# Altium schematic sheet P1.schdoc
size 594 x 419 mm; Symbol: Drawing-Symbol_A4; Company: 嘉立创EDA; Version: V1.0; Page Size: A4; @Project Name: BCIProject; @Update Date: 2026-07-25; @Create Date: 2026-07-25; Device: Drawing-Symbol_A4; @Board Name: Board1; @Page Name: P1; @Create Time: 19:43:27; @Page Count: 1; @Page No: 1; @Schematic Name: Schematic1; @Update Time: 19:43:27; @Assembly Variant: Basic; Border: 1; Title Block Position: 3; Size: A4; Width: 2338; Height: 1652; Region Start: 1; X Region Count: 6; Y Region Count: 4; Blade Width: 10
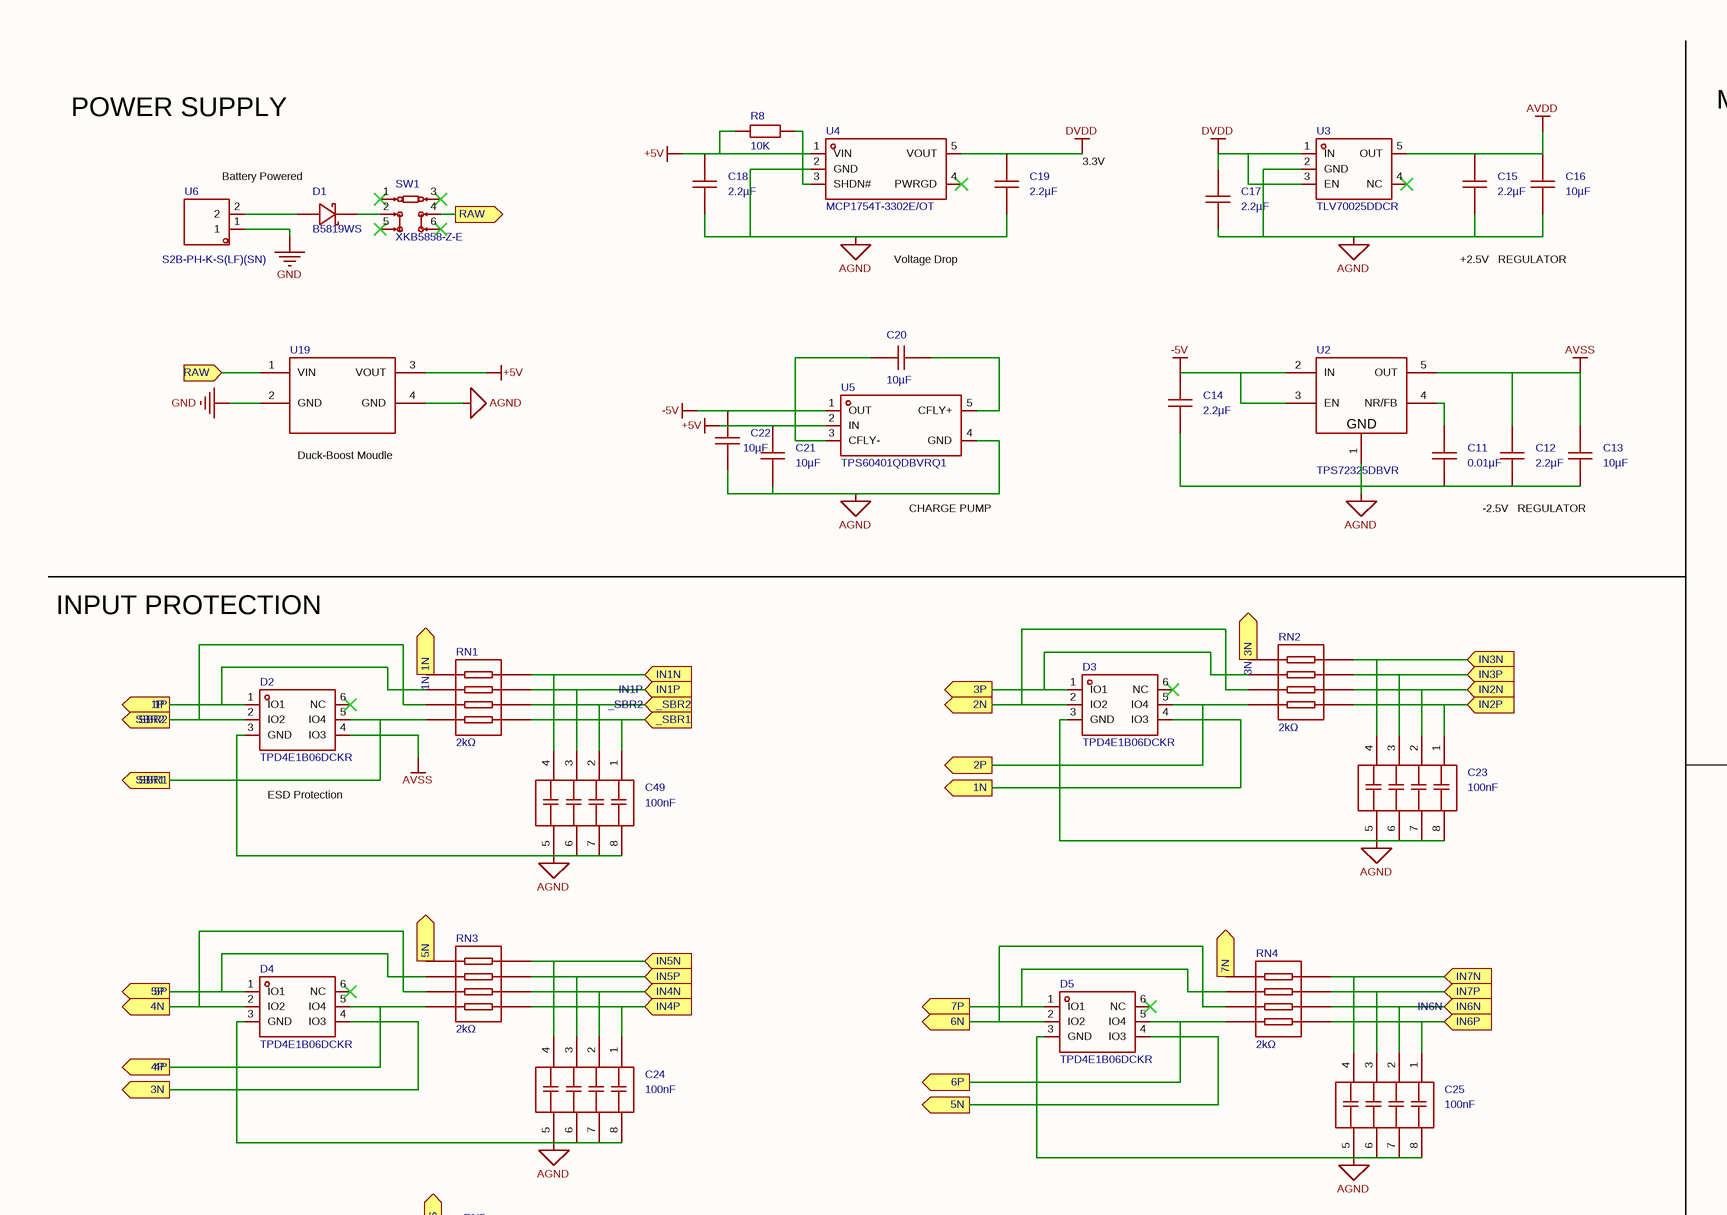
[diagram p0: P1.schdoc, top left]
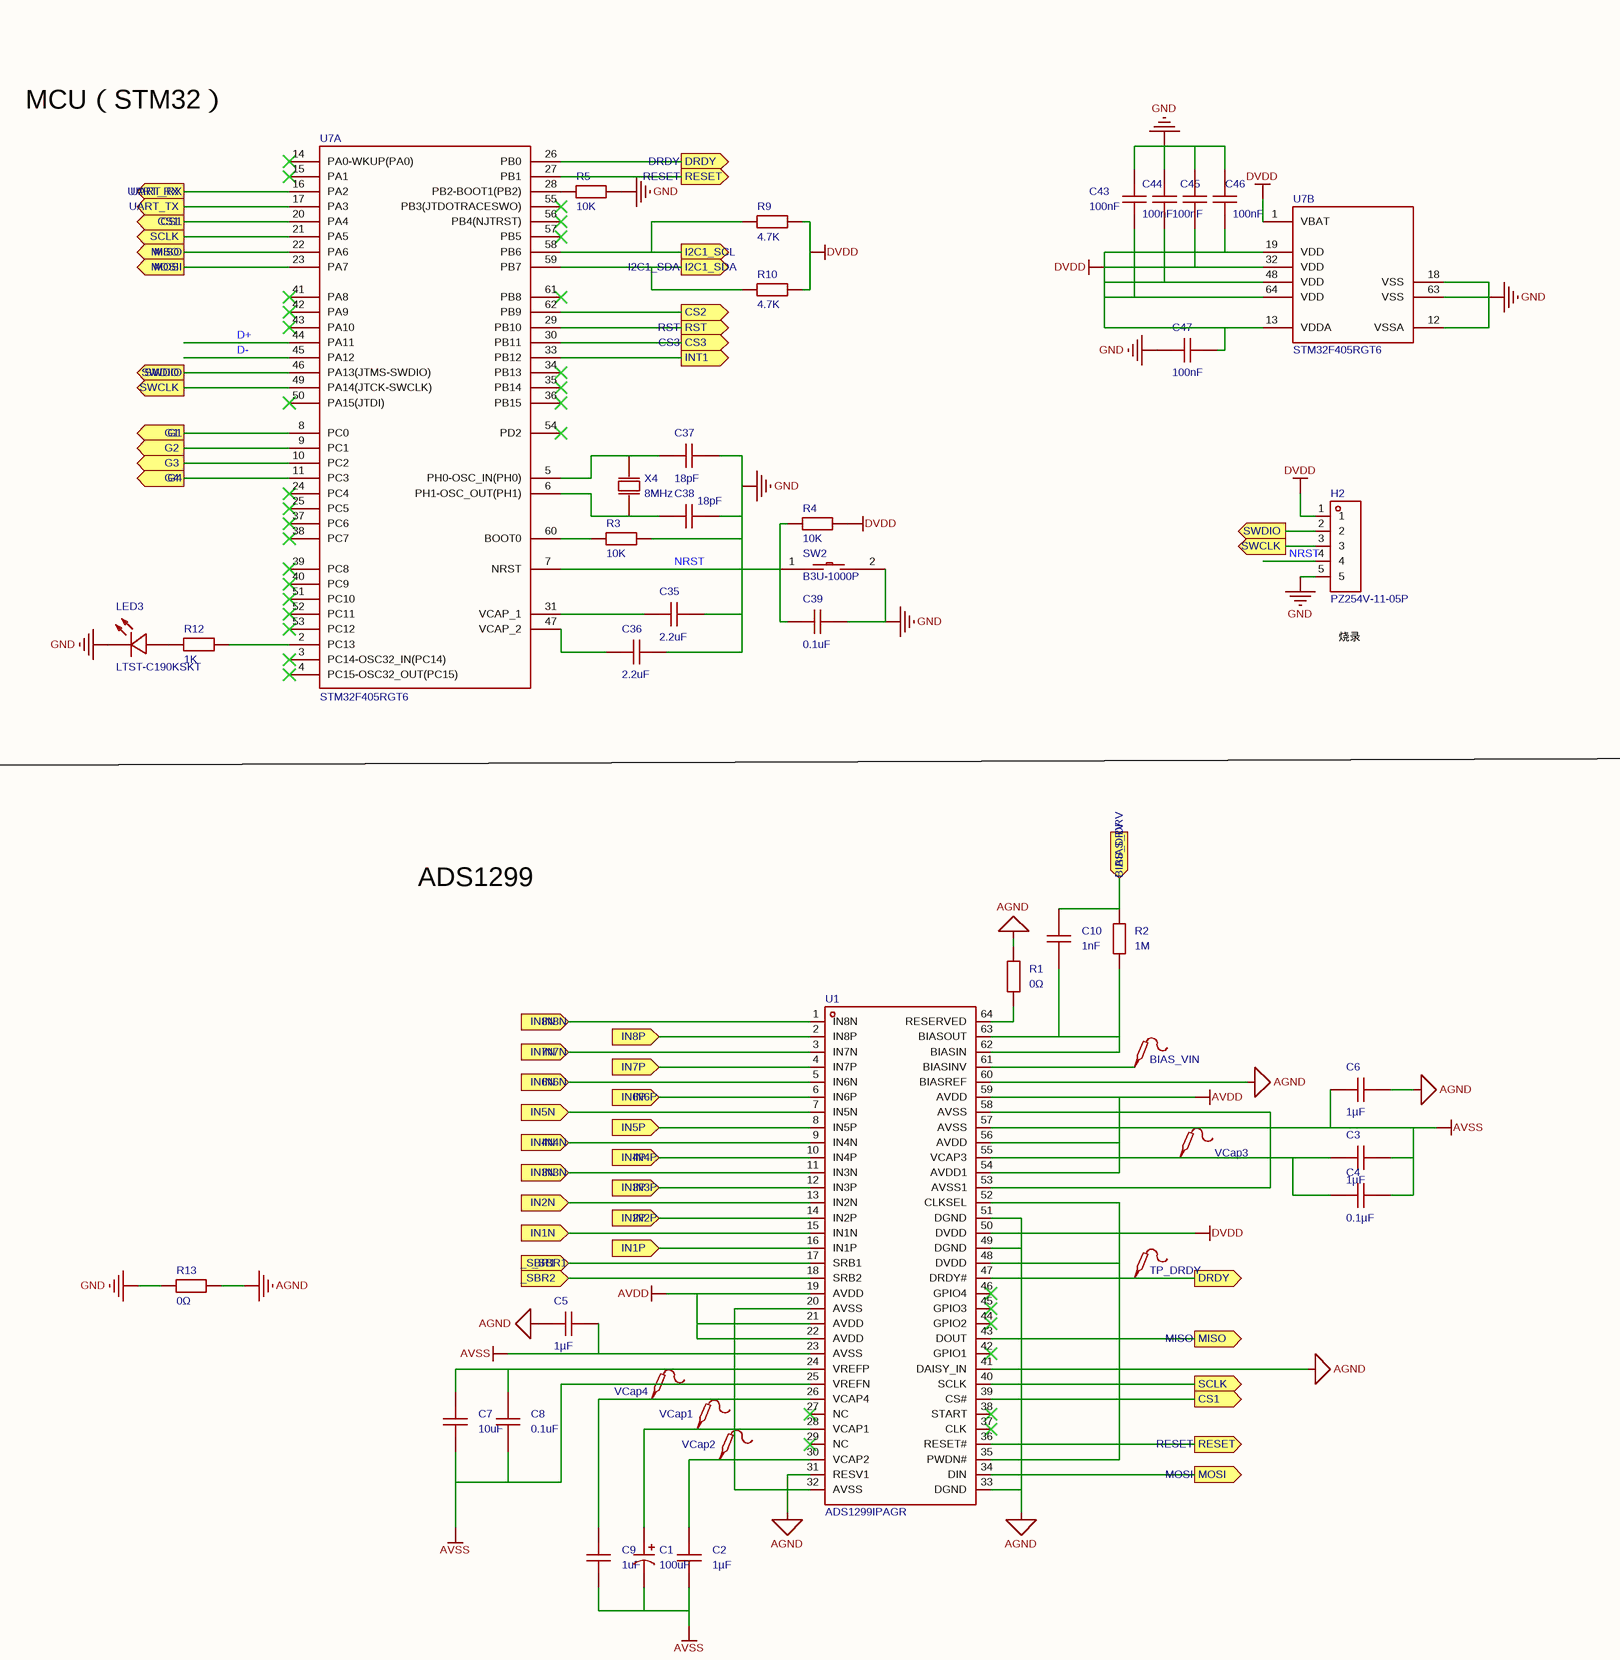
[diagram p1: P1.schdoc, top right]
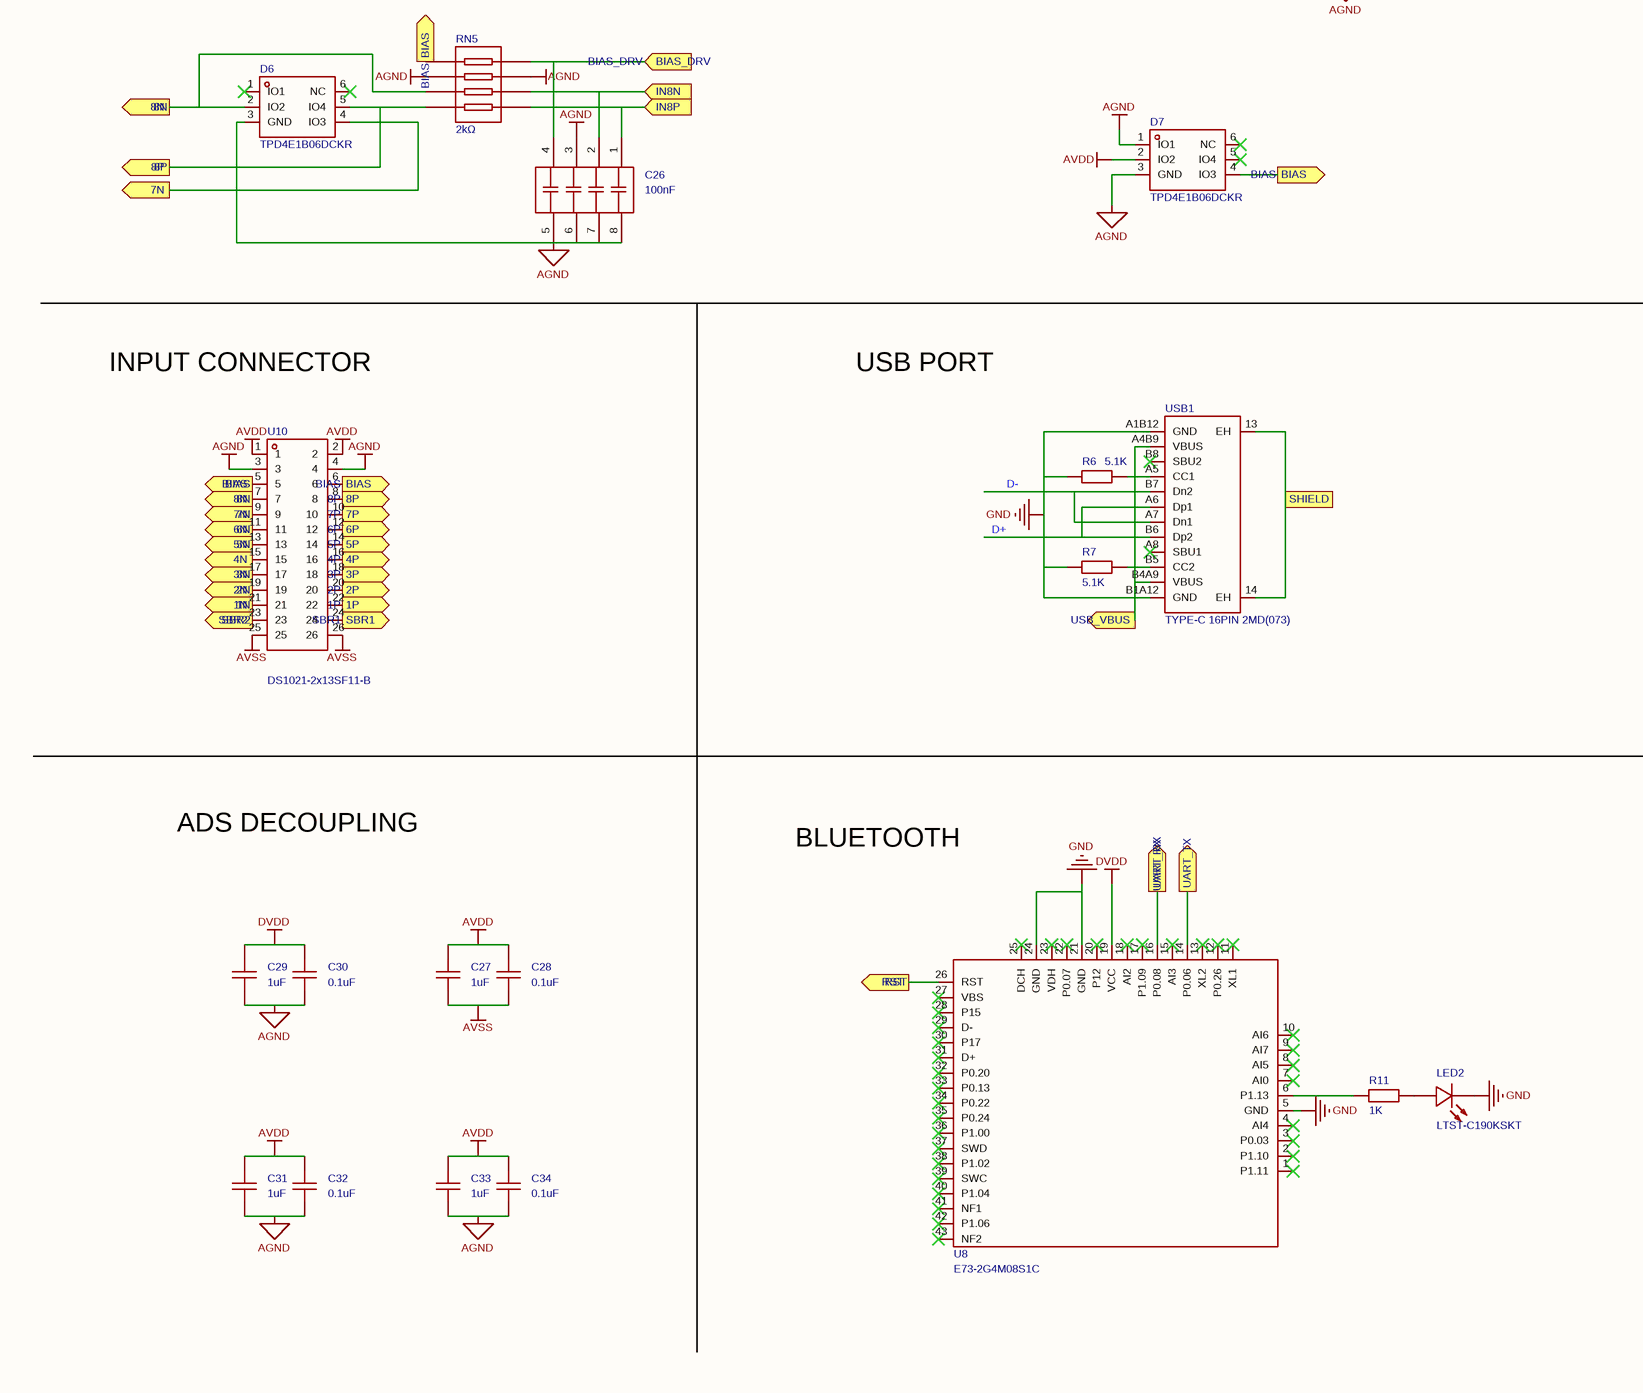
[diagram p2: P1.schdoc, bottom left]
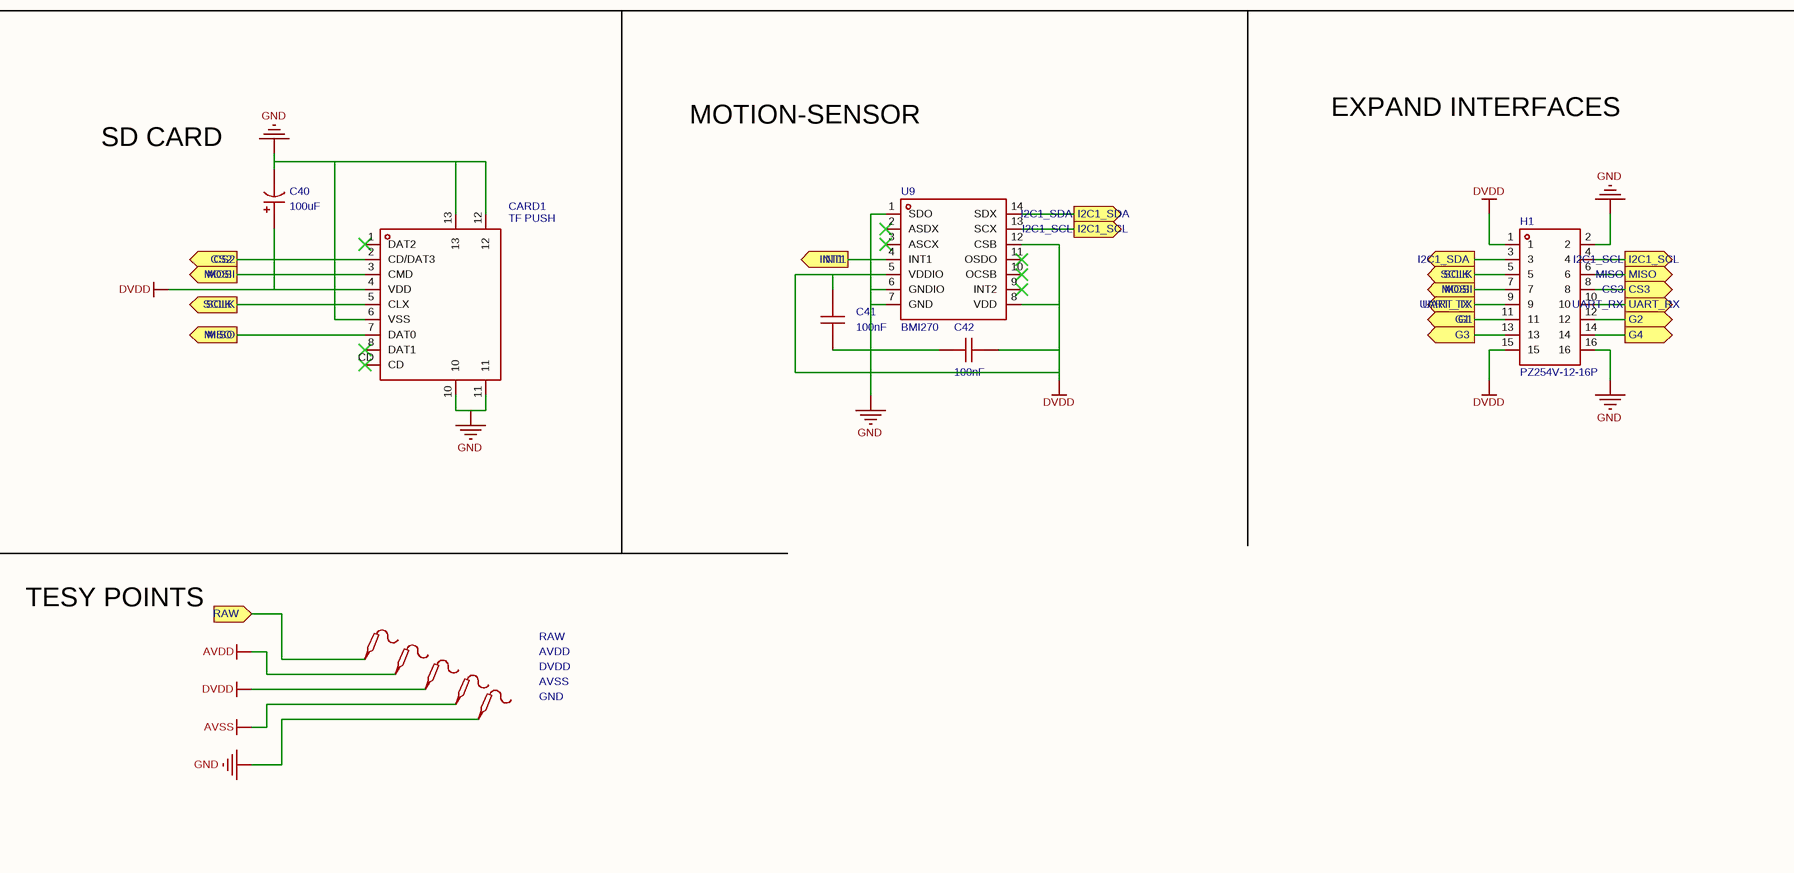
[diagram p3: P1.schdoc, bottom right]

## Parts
AVDD  (no value)  [Test-Point-0.5mm]
AVSS  (no value)  [Test-Point-0.5mm]
BIAS_VIN  (no value)  [Test-Point-0.5mm]
C1  100uF  [CAP-SMD_L7.3-W4.3-RD_177EC0013]
C2  1µF  [C0603]
C3  1µF  [C0603]
C4  0.1µF  [C0603]
C5  1µF  [C0603]
C6  1µF  [C0603]
C7  10uF  [C0603]
C8  0.1uF  [C0603]
C9  1uF  [C0603]
C10  1nF  [C0603]
C11  0.01µF  [C0603]
C12  2.2µF  [C0603]
C13  10µF  [C0603]
C14  2.2µF  [C0603]
C15  2.2µF  [C0603]
C16  10µF  [C0603]
C17  2.2µF  [C0603]
C18  2.2µF  [C0603]
C19  2.2µF  [C0603]
C20  10µF  [C0603]
C21  10µF  [C0603]
C22  10µF  [C0603]
C23  100nF  [CAP-ARRAY-SMD_6124-8P-L1.6-W3.2-BL]
C24  100nF  [CAP-ARRAY-SMD_6124-8P-L1.6-W3.2-BL]
C25  100nF  [CAP-ARRAY-SMD_6124-8P-L1.6-W3.2-BL]
C26  100nF  [CAP-ARRAY-SMD_6124-8P-L1.6-W3.2-BL]
C27  1uF  [C0603]
C28  0.1uF  [C0603]
C29  1uF  [C0603]
C30  0.1uF  [C0603]
C31  1uF  [C0603]
C32  0.1uF  [C0603]
C33  1uF  [C0603]
C34  0.1uF  [C0603]
C35  2.2uF  [C0603]
C36  2.2uF  [C0603]
C37  18pF  [C0603]
C38  18pF  [C0603]
C39  0.1uF  [C0603]
C40  100uF  [CAP-SMD_L7.3-W4.3-RD_177EC0013]
C41  100nF  [C0603]
C42  100nF  [C0603]
C43  100nF  [C0603]
C44  100nF  [C0603]
C45  100nF  [C0603]
C46  100nF  [C0603]
C47  100nF  [C0603]
C49  100nF  [CAP-ARRAY-SMD_6124-8P-L1.6-W3.2-BL]
CARD1  TF PUSH  [TF-SMD_TF-PUSH]
D1  B5819WS  [SOD-323_L1.7-W1.3-LS2.5-FD]
D2  TPD4E1B06DCKR  [SC-70-6_L2.2-W1.3-P0.65-LS2.1-BL]
D3  TPD4E1B06DCKR  [SC-70-6_L2.2-W1.3-P0.65-LS2.1-BL]
D4  TPD4E1B06DCKR  [SC-70-6_L2.2-W1.3-P0.65-LS2.1-BL]
D5  TPD4E1B06DCKR  [SC-70-6_L2.2-W1.3-P0.65-LS2.1-BL]
D6  TPD4E1B06DCKR  [SC-70-6_L2.2-W1.3-P0.65-LS2.1-BL]
D7  TPD4E1B06DCKR  [SC-70-6_L2.2-W1.3-P0.65-LS2.1-BL]
DVDD  (no value)  [Test-Point-0.5mm]
GND  (no value)  [Test-Point-0.5mm]
H1  PZ254V-12-16P  [HDR-TH_16P-P2.54-V-M-R2-C8-S2.54]
H2  PZ254V-11-05P  [HDR-TH_5P-P2.54-V-M]
LED2  LTST-C190KSKT  [LED0603-RD]
LED3  LTST-C190KSKT  [LED0603-RD]
R1  0Ω  [R0603]
R2  1M  [R0603]
R3  10K  [R0603]
R4  10K  [R0603]
R5  10K  [R0603]
R6  5.1K  [R0603]
R7  5.1K  [R0603]
R8  10K  [R0603]
R9  4.7K  [R0603]
R10  4.7K  [R0603]
R11  1K  [R0603]
R12  1K  [R0603]
R13  0Ω  [R0402]
RAW  (no value)  [Test-Point-0.5mm]
RN1  2kΩ  [RES-ARRAY-SMD_0603-8P-L3.2-W1.6-BL]
RN2  2kΩ  [RES-ARRAY-SMD_0603-8P-L3.2-W1.6-BL]
RN3  2kΩ  [RES-ARRAY-SMD_0603-8P-L3.2-W1.6-BL]
RN4  2kΩ  [RES-ARRAY-SMD_0603-8P-L3.2-W1.6-BL]
RN5  2kΩ  [RES-ARRAY-SMD_0603-8P-L3.2-W1.6-BL]
SW1  XKB5858-Z-E  [SW-TH_XKB5858-Z-E]
SW2  B3U-1000P  [KEY-SMD_B3U-1000PM]
TP_DRDY  (no value)  [Test-Point-0.5mm]
U1  ADS1299IPAGR  [TQFP-64_L10.0-W10.0-P0.50-LS12.0-TL]
U2  TPS72325DBVR  [SOT-23-5_L3.0-W1.7-P0.95-LS2.8-BR]
U3  TLV70025DDCR  [SOT-23-5_L3.0-W1.7-P0.95-LS2.8-BR]
U4  MCP1754T-3302E/OT  [SOT-23-5_L2.9-W1.6-P0.95-LS2.9-BL]
U5  TPS60401QDBVRQ1  [SOT-23-5_L2.9-W1.6-P0.95-LS2.8-BR]
U6  S2B-PH-K-S(LF)(SN)  [CONN-TH_S2B-PH-K-S-LF-SN]
U7  STM32F405RGT6  [LQFP-64_L10.0-W10.0-P0.50-LS12.0-BL]  (parts A,B of 2)
U8  E73-2G4M08S1C  [WIRELM-SMD_E73-2G4M08S1C]
U9  BMI270  [LGA-14_L3.0-W2.5-P0.50-BR]
U10  DS1021-2x13SF11-B  [HDR-TH_26P-P2.54-V-M-R2-C13-S2.54]
U19  (no value)  [tps63070模块]
USB1  TYPE-C 16PIN 2MD(073)  [USB-C-SMD_TYPE-C-16PIN-2MD-073]
VCap1  (no value)  [Test-Point-0.5mm]
VCap2  (no value)  [Test-Point-0.5mm]
VCap3  (no value)  [Test-Point-0.5mm]
VCap4  (no value)  [Test-Point-0.5mm]
X4  8MHz  [CRYSTAL-SMD_L5.0-W3.2]

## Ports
1N (out), 1P (out), 2N (out), 2P (out), 3N (out), 3P (out), 4N (out), 4P (out), 5N (out), 5P (out), 6N (out), 6P (out), 7N (out), 7P (out), 8N (out), 8P (out), _SBR1 (in), _SBR2 (in), BIAS (out), BIAS_DRV (in), CS1 (out), CS2 (out), CS3 (out), DRDY (out), G1 (out), G2 (out), G3 (out), G4 (out), I2C1_SCL (out), I2C1_SDA (out), IN1N (in), IN1P (in), IN2N (in), IN2P (in), IN3N (in), IN3P (in), IN4N (in), IN4P (in), IN5N (in), IN5P (in), IN6N (in), IN6P (in), IN7N (in), IN7P (in), IN8N (in), IN8P (in), INT1 (out), MISO (out), MOSI (out), RAW (in), RAW (out), RESET (out), RST (out), SBR1 (out), SBR2 (out), SCLK (out), SHIELD (out), SWCLK (out), SWDIO (out), UART_RX (out), UART_TX (out), USB_VBUS (out)

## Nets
+5V: C18.2 C21.2 R8.1 U4.1(VIN) U5.2(IN) U19.3(VOUT)
-5V: C14.2 C22.2 U2.2(IN) U2.3(EN) U5.1(OUT)
AGND: C5.1 C6.2 C11.1 C12.1 C13.2 C14.1 C15.1 C16.1 C17.1 C18.1 C19.1 C21.1 C22.1 C23.5 C23.6 C23.7 C23.8 C24.5 C24.6 C24.7 C24.8 C25.5 C25.6 C25.7 C25.8 C26.3 C26.5 C26.6 C26.7 C26.8 C29.1 C30.1 C31.1 C32.1 C33.1 C34.1 C49.5 C49.6 C49.7 C49.8 D2.3(GND) D3.3(GND) D4.3(GND) D5.3(GND) D6.3(GND) D7.1(IO1) D7.3(GND) R1.2 R13.1 RN5.2 RN5.7 U1.31(RESV1) U1.33(DGND) U1.41(DAISY_IN) U1.49(DGND) U1.51(DGND) U1.60(BIASREF) U2.1(GND) U3.2(GND) U4.2(GND) U5.4(GND) U10.3 U10.4 U19.4(GND)
AVDD: AVDD.1 C15.2 C16.2 C27.2 C28.2 C31.2 C32.2 C33.2 C34.2 D7.2(IO2) U1.19(AVDD) U1.21(AVDD) U1.22(AVDD) U1.54(AVDD1) U1.56(AVDD) U1.59(AVDD) U3.5(OUT) U10.1 U10.2
AVSS: AVSS.1 C1.1 C2.1 C3.2 C4.2 C5.2 C6.1 C7.1 C8.1 C9.1 C12.2 C13.1 C27.1 C28.1 D2.4(IO3) U1.20(AVSS) U1.23(AVSS) U1.25(VREFN) U1.32(AVSS) U1.53(AVSS1) U1.57(AVSS) U1.58(AVSS) U2.5(OUT) U10.25 U10.26
DVDD: C17.2 C19.2 C29.2 C30.2 C40.2 C41.2 C42.2 C43.1 C44.1 C45.1 C46.1 C47.2 CARD1.4(VDD) DVDD.1 H1.1 H1.15 H2.1 R4.2 R9.2 R10.2 U1.35(PWDN#) U1.48(DVDD) U1.50(DVDD) U1.52(CLKSEL) U3.1(IN) U3.3(EN) U4.5(VOUT) U7.1(VBAT) U7.13(VDDA) U7.19(VDD) U7.32(VDD) U7.48(VDD) U7.64(VDD) U8.19(VCC) U9.5(VDDIO) U9.8(VDD) U9.12(CSB)
GND: C35.2 C36.2 C37.2 C38.2 C39.2 C40.1 C41.1 C42.1 C43.2 C44.2 C45.2 C46.2 C47.1 CARD1.6(VSS) CARD1.10 CARD1.11 CARD1.12 CARD1.13 GND.1 H1.2 H1.16 H2.5 LED2.1(-) LED3.1(-) R3.2 R5.2 R6.1 R7.1 R13.2 SW2.2 U6.1 U7.12(VSSA) U7.18(VSS) U7.63(VSS) U8.5(GND) U8.21(GND) U8.24(GND) U9.1(SDO) U9.6(GNDIO) U9.7(GND) U19.2(GND) USB1.A1B12(GND) USB1.B1A12(GND)
1N: D3.4(IO3) RN1.1 U10.21 ; port 1N
1P: D2.1(IO1) RN1.2 U10.22 ; port 1P
2N: D3.2(IO2) RN2.3 U10.19 ; port 2N
2P: D3.5(IO4) RN2.4 U10.20 ; port 2P
3N: D4.4(IO3) RN2.1 U10.17 ; port 3N
3P: D3.1(IO1) RN2.2 U10.18 ; port 3P
4N: D4.2(IO2) RN3.3 U10.15 ; port 4N
4P: D4.5(IO4) RN3.4 U10.16 ; port 4P
5N: D5.4(IO3) RN3.1 U10.13 ; port 5N
5P: D4.1(IO1) RN3.2 U10.14 ; port 5P
6N: D5.2(IO2) RN4.3 U10.11 ; port 6N
6P: D5.5(IO4) RN4.4 U10.12 ; port 6P
7N: D6.4(IO3) RN4.1 U10.9 ; port 7N
7P: D5.1(IO1) RN4.2 U10.10 ; port 7P
8N: D6.2(IO2) RN5.3 U10.7 ; port 8N
8P: D6.5(IO4) RN5.4 U10.8 ; port 8P
_SBR1: C49.1 RN1.5 U1.17(SRB1) ; port _SBR1
_SBR2: C49.2 RN1.6 U1.18(SRB2) ; port _SBR2
BIAS: D7.4(IO3) RN5.1 U10.5 U10.6 ; port BIAS
BIAS_DRV: C10.2 C26.4 R2.2 RN5.8 ; port BIAS_DRV
CS1: U1.39(CS#) U7.20(PA4) ; port CS1
CS2: CARD1.2(CD/DAT3) U7.62(PB9) ; port CS2
CS3: H1.8 U7.30(PB11) ; port CS3
D+: U7.44(PA11) USB1.A6(Dp1) USB1.B6(Dp2)
D-: U7.45(PA12) USB1.A7(Dn1) USB1.B7(Dn2)
DRDY: TP_DRDY.1 U1.47(DRDY#) U7.26(PB0) ; port DRDY
G1: H1.11 U7.8(PC0) ; port G1
G2: H1.12 U7.9(PC1) ; port G2
G3: H1.13 U7.10(PC2) ; port G3
G4: H1.14 U7.11(PC3) ; port G4
I2C1_SCL: H1.4 R9.1 U7.58(PB6) U9.13(SCX) ; port I2C1_SCL
I2C1_SDA: H1.3 R10.1 U7.59(PB7) U9.14(SDX) ; port I2C1_SDA
IN1N: C49.4 RN1.8 U1.15(IN1N) ; port IN1N
IN1P: C49.3 RN1.7 U1.16(IN1P) ; port IN1P
IN2N: C23.2 RN2.6 U1.13(IN2N) ; port IN2N
IN2P: C23.1 RN2.5 U1.14(IN2P) ; port IN2P
IN3N: C23.4 RN2.8 U1.11(IN3N) ; port IN3N
IN3P: C23.3 RN2.7 U1.12(IN3P) ; port IN3P
IN4N: C24.2 RN3.6 U1.9(IN4N) ; port IN4N
IN4P: C24.1 RN3.5 U1.10(IN4P) ; port IN4P
IN5N: C24.4 RN3.8 U1.7(IN5N) ; port IN5N
IN5P: C24.3 RN3.7 U1.8(IN5P) ; port IN5P
IN6N: C25.2 RN4.6 U1.5(IN6N) ; port IN6N
IN6P: C25.1 RN4.5 U1.6(IN6P) ; port IN6P
IN7N: C25.4 RN4.8 U1.3(IN7N) ; port IN7N
IN7P: C25.3 RN4.7 U1.4(IN7P) ; port IN7P
IN8N: C26.2 RN5.6 U1.1(IN8N) ; port IN8N
IN8P: C26.1 RN5.5 U1.2(IN8P) ; port IN8P
INT1: U7.33(PB12) U9.4(INT1) ; port INT1
MISO: CARD1.7(DAT0) H1.6 U1.43(DOUT) U7.22(PA6) ; port MISO
MOSI: CARD1.3(CMD) H1.7 U1.34(DIN) U7.23(PA7) ; port MOSI
NRST: C39.1 H2.4 R4.1 SW2.1 U7.7(NRST)
RAW: RAW.1 SW1.4 U19.1(VIN) ; port RAW
RESET: U1.36(RESET#) U7.27(PB1) ; port RESET
RST: U7.29(PB10) U8.26(RST) ; port RST
SBR1: D2.5(IO4) RN1.4 U10.24 ; port SBR1
SBR2: D2.2(IO2) RN1.3 U10.23 ; port SBR2
SCLK: CARD1.5(CLX) H1.5 U1.40(SCLK) U7.21(PA5) ; port SCLK
SHIELD: USB1.13(EH) USB1.14(EH) ; port SHIELD
SWCLK: H2.3 U7.49(PA14(JTCK-SWCLK)) ; port SWCLK
SWDIO: H2.2 U7.46(PA13(JTMS-SWDIO)) ; port SWDIO
UART_RX: H1.10 U7.16(PA2) U8.16(P0.08) ; port UART_RX
UART_TX: H1.9 U7.17(PA3) U8.14(P0.06) ; port UART_TX
USB_VBUS: USB1.A4B9(VBUS) USB1.B4A9(VBUS) ; port USB_VBUS
NetBIAS_VIN_1: BIAS_VIN.1 U1.61(BIASINV)
NetC1_2: C1.2 U1.28(VCAP1) VCap1.1
NetC2_2: C2.2 U1.30(VCAP2) VCap2.1
NetC3_1: C3.1 C4.1 U1.55(VCAP3) VCap3.1
NetC7_2: C7.2 C8.2 U1.24(VREFP)
NetC9_2: C9.2 U1.26(VCAP4) VCap4.1
NetC10_1: C10.1 R2.1 U1.62(BIASIN) U1.63(BIASOUT)
NetC11_2: C11.2 U2.4(NR/FB)
NetC20_1: C20.1 U5.3(CFLY-)
NetC20_2: C20.2 U5.5(CFLY+)
NetC35_1: C35.1 U7.31(VCAP_1)
NetC36_1: C36.1 U7.47(VCAP_2)
NetC37_1: C37.1 U7.5(PH0-OSC_IN(PH0)) X4.2(OSC2)
NetC38_1: C38.1 U7.6(PH1-OSC_OUT(PH1)) X4.1(OSC1)
NetD1_1: D1.1(A) U6.2
NetD1_2: D1.2(K) SW1.2
NetLED2_2: LED2.2(+) R11.2
NetLED3_2: LED3.2(+) R12.2
NetR1_1: R1.1 U1.64(RESERVED)
NetR3_1: R3.1 U7.60(BOOT0)
NetR5_1: R5.1 U7.28(PB2-BOOT1(PB2))
NetR6_2: R6.2 USB1.A5(CC1)
NetR7_2: R7.2 USB1.B5(CC2)
NetR8_2: R8.2 U4.3(SHDN#)
NetR11_1: R11.1 U8.6(P1.13)
NetR12_1: R12.1 U7.2(PC13)

Not connected (* = marked no-connect by the designer): CARD1 1(DAT2)* 8(DAT1)* CD*; D2 6(NC)*; D3 6(NC)*; D4 6(NC)*; D5 6(NC)*; D6 1(IO1)* 6(NC)*; D7 5(IO4)* 6(NC)*; SW1 1* 3* 5* 6*; U1 27(NC)* 29(NC)* 37(CLK)* 38(START)* 42(GPIO1)* 44(GPIO2)* 45(GPIO3)* 46(GPIO4)*; U3 4(NC)*; U4 4(PWRGD)*; U7 3(PC14-OSC32_IN(PC14))* 4(PC15-OSC32_OUT(PC15))* 14(PA0-WKUP(PA0))* 15(PA1)* 24(PC4)* 25(PC5)* 34(PB13)* 35(PB14)* 36(PB15)* 37(PC6)* 38(PC7)* 39(PC8)* 40(PC9)* 41(PA8)* 42(PA9)* 43(PA10)* 50(PA15(JTDI))* 51(PC10)* 52(PC11)* 53(PC12)* 54(PD2)* 55(PB3(JTDOTRACESWO))* 56(PB4(NJTRST))* 57(PB5)* 61(PB8)*; U8 1(P1.11)* 2(P1.10)* 3(P0.03)* 4(AI4)* 7(AI0)* 8(AI5)* 9(AI7)* 10(AI6)* 11(XL1)* 12(P0.26)* 13(XL2)* 15(AI3)* 17(P1.09)* 18(AI2)* 20(P12)* 22(P0.07)* 23(VDH)* 25(DCH)* 27(VBS)* 28(P15)* 29(D-)* 30(P17)* 31(D+)* 32(P0.20)* 33(P0.13)* 34(P0.22)* 35(P0.24)* 36(P1.00)* 37(SWD)* 38(P1.02)* 39(SWC)* 40(P1.04)* 41(NF1)* 42(P1.06)* 43(NF2)*; U9 2(ASDX)* 3(ASCX)* 9(INT2)* 10(OCSB)* 11(OSDO)*; USB1 A8(SBU1)* B8(SBU2)*

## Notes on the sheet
- POWER SUPPLY
- MCU（STM32）
- Battery Powered
- 3.3V
- Voltage Drop
- +2.5V   REGULATOR
- (near U19) Duck-Boost Moudle
- CHARGE PUMP
- -2.5V   REGULATOR
- INPUT PROTECTION
- (near H2) 烧录
- (near D2) ESD Protection
- ADS1299
- INPUT CONNECTOR
- USB PORT
- EXPAND INTERFACES
- SD CARD
- MOTION-SENSOR
- ADS DECOUPLING
- BLUETOOTH
- TESY POINTS

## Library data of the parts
AVDD AVSS BIAS_VIN DVDD GND RAW TP_DRDY VCap1-VCap4 = Test-Point: Test Point 测试点; AddInBom: yes
C1 C40 = TA10R0M100AR40: 容值:100uF;精度:±20%;额定电压:10V;等效串联电阻(ESR):40mΩ@100kHz;; Manufacturer: JIERR(捷而瑞); AddInBom: yes; ModelId: 57a4bba5c484496b9c973bf4fd310b240819f05c4eef4c71ace90d822a990e87; ModelTransform: 287.401,169.291,0,0,0,0,0,0,0; Tolerance: ±20%; Voltage Rating: 10V; Current - Leakage: 100uA@20℃,2min; Ripple Current: 3.2A@100kHz
C2-C22 C27-C39 C41-C47 = CAP_0603: Symbol: Capacitance; ConvertToPcb: yes; ModelId: ac125912035d415993ca9572d50418b10819f05c4eef4c71ace90d822a990e87; ModelName: C0603_L1.6-W0.8-H0.8; ModelTransform: 62.992,31.496,0,0,0,0,0,0,0
C23-C26 C49 = 6124B104K500NT: 容值:100nF;精度:±10%;额定电压:50V;温度系数:X7R;电路形式:独立;; Manufacturer: FH(风华); 3D Model: f2e49f0a400c466dbdd055404a35ee7a; 3D Model Transform: 125.984,63.7794,0,0,0,0,0,0,0; Tolerance: ±10%; Rated Voltage: 50V; Temperature Coefficient: X7R; Number of Capacitors: 4; Circuit Type: 独立; AddInBom: yes; ModelName: CAP-ARRAY-SMD_L1.6-W3.2-H0.9-P0.8
CARD1 = TF PUSH: 卡连接方式:自弹式;卡类型:MicroSD卡(TF卡);连接器类型:卡座;本体最大高度:2mm;工作温度:-25℃~+90℃;; Manufacturer: SHOU HAN(首韩); AddInBom: yes; ModelId: 2d6270e77c9a43c6bb0aca962ba811a20819f05c4eef4c71ace90d822a990e87; ModelTransform: 635.826,598.424,0,0,0,0,0.002,-82.441,-23.622; Card Connection Mode: 自弹式; Connector Type: 卡座; Additional Card Detection Pins: 无
D1 = B5819WS_C7420331: 二极管配置:独立式;正向压降(Vf):600mV@1.0A;直流反向耐压(Vr):40V;整流电流:1A;; Manufacturer: R+O(宏嘉诚); AddInBom: yes; ModelId: 0f2f330c645944df9245ac3c3fec34560819f05c4eef4c71ace90d822a990e87; ModelTransform: 98.425,49.2125,0,180,0,0,0,0,0; Diode Configuration: 独立式; Voltage - DC Reverse(Vr): 40V; Current - Rectified: 1A; Reverse Leakage Current (Ir): 1mA@40V; Operating Junction Temperature Range: -55℃~+150℃; Non-Repetitive Peak Forward Surge Current: 10A
D2-D7 = TPD4E1B06DCKR: TPD4E1B06 采用 SOT 和 SC70 封装且具有 0.5nA 最大泄漏电流的四路 0.7pF、±5.5V、±12kV ESD 保护二极管; Manufacturer: TI(德州仪器); AddInBom: yes; ModelId: 7779600a2eb94c6fae04993c10cd58cb0819f05c4eef4c71ace90d822a990e87; ModelName: SC-70-6_L2.0-W1.3-H1.0-P0.65; ModelTransform: 82.677,78.74,0,90,0,0,0,0.0005,0
H1 = PZ254V-12-16P: 插针结构:2x8P;间距:2.54mm;行距:2.54mm;圆针/方针:方针;安装方式:直插;排数:双排;总PIN位数:16P;额定电流:-;额定电压:-;配合针长度:6mm;塑高:2.5mm;端接针长度:3mm;触头材质:黄铜;触头镀层:-;工作温度:-40℃~+105℃;颜色:黑色;; Manufacturer: XFCN(兴飞); AddInBom: yes; ModelId: 4229ed04564d49dfa51d40f734d422b60819f05c4eef4c71ace90d822a990e87; ModelName: HDR2.54-M-LI-2X8P; ModelTransform: 799.99844,200,0,0,0,0,0,0,-118.11; Pin Structure: 2x8P; Pitch: 2.54mm; Circluar Pins/Square Pins: 方针
H2 = PZ254V-11-05P: 插针结构:1x5P;间距:2.54mm;行距:-;圆针/方针:方针;安装方式:直插;排数:单排;总PIN位数:5P;额定电流:3A;额定电压:250V;配合针长度:6mm;塑高:2.5mm;端接针长度:3mm;触头材质:黄铜;触头镀层:-;工作温度:-40℃~+105℃;颜色:黑色;; Manufacturer: XFCN(兴飞); AddInBom: yes; ModelId: 47d466e4a34f4fc5bc626cf773a24dd50819f05c4eef4c71ace90d822a990e87; ModelName: HDR-TH_5P-P2.54-M-LI-1X5P; ModelTransform: 499.999,100,0,0,0,0,0,0,-118.11; Pin Structure: 1x5P; Pitch: 2.54mm; Circluar Pins/Square Pins: 方针; Current Rating: 3A; Voltage Rating (Max): 250V
LED2 LED3 = LTST-C190KSKT: 灯头类型:-;发光颜色:黄色;正向压降(Vf):2.1V;功率:75mW;正向电流:20mA;波长:584.5nm~597nm;二极管配置:独立二极管;透镜颜色:无色透明透镜;色温:-;发光强度:104mcd;发光角度:130°;载带方式:-;工作温度:-30℃~+85℃;; Manufacturer: LITEON(光宝); AddInBom: yes; ModelId: 1f0d29a91be547639d425604e9b96ebb0819f05c4eef4c71ace90d822a990e87; ModelTransform: 63.7794,32.283,0,0,0,0,0,0,0; Illumination Color: 黄色; Voltage - Forward(Vf): 2.1V; Power(Watts): 75mW; Forward Current: 20mA; Peak Wavelength: 588nm; Diode Configuration: 独立二极管; Lens Color: 无色透明透镜; Luminous Intensity: 104mcd; Viewing Angle: 130°
R1-R12 = Res_0603: Symbol: 电阻; ConvertToPcb: yes; ModelId: fc143cca1e79419f9cd78b61e9279f080819f05c4eef4c71ace90d822a990e87; ModelTransform: 31.8897,63.7794,0,90,0,0,0,0,0
R13 = 0402WGF0000TCE: 电阻类型:厚膜电阻;阻值:0Ω;精度:±1%;功率:62.5mW;最大工作电压:50V;温度系数:±800ppm/℃;; Manufacturer: UNI-ROYAL(厚声); 3D Model: 671aefced39d4c318694bba8bd8efd39; 3D Model Transform: 39.37,19.685,0,0,0,0,0,0.0005,0; Tolerance: ±1%; Power(Watts): 62.5mW; Overload Voltage (Max): 50V; AddInBom: yes; ModelName: R0402_L1.0-W0.5-H0.5
RN1-RN5 = 4D03WGF2001T5E: 电阻器数:4;阻值:2kΩ;精度:±1%;单个元件功率:62.5mW;温度系数:±200ppm/℃;; Manufacturer: UNI-ROYAL(厚声); AddInBom: yes; ModelId: edf39f9a2dca4b9a94267f442dd4f95a0819f05c4eef4c71ace90d822a990e87; ModelName: R0603-8P_L3.2-W1.6-H0.6; ModelTransform: 125.984,62.992,0,0,0,0,0,0,0; Number of Resistors: 4; Tolerance: ±1%; Power(Watts): 62.5mW
SW1 = XKB5858-Z-E: 自锁/无锁:自锁;安装方式:弯插;触点电流:100mA;额定电压:30V;带灯:不带;作用力:2.5N;工作寿命:10万次;; Manufacturer: XKB Connection(中国星坤); AddInBom: yes; ModelId: 1a871d5f56d74906a4af367e0a8a0ef60819f05c4eef4c71ace90d822a990e87; ModelTransform: 248.031,409.448,0,180,0,0,0,141.85,-78.74; Self Lock / No Lock: 自锁; Actuator Style: 方形按钮; Contact Current: 100mA; Voltage Rating: 30V; Actuator/Cap Color: 白色; With Lamp: 不带; Operating Force: 2.5N; Life: 10万次
SW2 = B3U-1000P: 电路结构:单刀单掷;按钮形状:圆形按钮;作用力:1.53N;安装方式:立贴;开关长度:3mm;开关宽度:2.5mm;开关高度:1.6mm;触点电流:50mA;额定电压:12V;带灯:-;工作寿命:-;; Manufacturer: OMRON(欧姆龙); AddInBom: yes; ModelId: 4a122f942e8c428cab657e97b0b9ae700819f05c4eef4c71ace90d822a990e87; ModelName: KEY-SMD_2P-L3.0-W2.5-H1.6-LS4.0; ModelTransform: 157.48,98.425,0,0,0,0,0,0,0; Circuit: 单刀单掷; Actuator Style: 圆形按钮; Operating Force: 1.53N; Switch Height: 1.6mm; Contact Current: 50mA; Voltage Rating: 12V
U1 = ADS1299IPAGR: 工作电压:4.75V~5.25V;; Manufacturer: TI(德州仪器); AddInBom: yes; ModelId: 8d2ba6bfb2a14fb7921a74871619a1850819f05c4eef4c71ace90d822a990e87; ModelName: TQFP-64_L10.0-W10.0-H1.2-LS12.0-P0.50; ModelTransform: 473.00941,473.00941,0,0,0,0,0.039,0,0; Resolution(Bits): 24位; Gain Drift: 3ppm/℃; S/N Ratio: 121dB; Data rate: 16000Hz; Clock Frequency: 2.048MHz；1.5MHz~2.048MHz; Voltage Reference Value: 4.5V; Voltage Reference Drift: 35ppm/℃; Quiescent Current (Iq): 20uA; Interface: SPI
U2 = TPS72325DBVR: 输出极性:负极;工作电压:2.7V;输出电压:2.5V;输出电流:200mA;电源纹波抑制比(PSRR):65dB@(1kHz)；48dB@(10kHz);输出类型:固定;; Manufacturer: TI(德州仪器); AddInBom: yes; ModelId: 0a2a1b8f50944f73965918ad6e5fe1670819f05c4eef4c71ace90d822a990e87; ModelName: SOT-23-5_L2.9-W1.6-H1.1-LS2.8-P0.95; ModelTransform: 114.173,109.636,0,180,0,0,0,0,0; Output Configuration: 负极; Voltage - Supply: 2.7V; Output Voltage: 2.5V; Output Current: 200mA; Voltage Dropout: 500mV@(200mA); standby current: 130uA; Noise: 60uVrms; Output Type: 固定; Number of Outputs: 1
U3 = TLV70025DDCR: 输出极性:正极;工作电压:5.5V;输出电压:2.5V;输出电流:200mA;电源纹波抑制比(PSRR):68dB@(1kHz);输出类型:固定;; Manufacturer: TI(德州仪器); AddInBom: yes; ModelId: 0a2a1b8f50944f73965918ad6e5fe1670819f05c4eef4c71ace90d822a990e87; ModelName: SOT-23-5_L2.9-W1.6-H1.1-LS2.8-P0.95; ModelTransform: 114.173,109.636,0,180,0,0,0,0,0; Output Configuration: 正极; Voltage - Supply: 5.5V; Output Voltage: 2.5V; Output Current: 200mA; Voltage Dropout: 250mV@(200mA); standby current: 31uA; Noise: 48uVrms; Output Type: 固定; Number of Outputs: 1
U4 = MCP1754T-3302E/OT: 输出类型:固定;工作电压:16V;输出电压:3.3V;输出电流:150mA;电源纹波抑制比(PSRR):72dB@(1kHz);输出极性:正极;; Manufacturer: MICROCHIP(美国微芯); AddInBom: yes; ModelId: f208335ea6894ff1b04bfab971ca745a0819f05c4eef4c71ace90d822a990e87; ModelTransform: 114.173,114.173,0,0,0,0,0,-0.003,0; Output Type: 固定; Voltage - Supply: 16V; Output Voltage: 3.3V; Output Current: 150mA; Voltage Dropout: 500mV@(150mA); standby current: 56uA; Output Configuration: 正极; Number of Outputs: 1
U5 = TPS60401QDBVRQ1: TPS60401-Q1 具有 20kHz 固定频率的汽车类非稳压 60mA 电荷泵电压逆变器; Manufacturer: TI(德州仪器); AddInBom: yes; ModelId: 7ba65df16e7b4570af156e925f9c37fe0819f05c4eef4c71ace90d822a990e87; ModelTransform: 114.173,114.173,0,90,0,0,0,0,0; Function: 反相; Operating Voltage: 1.8V~5.25V; Quiescent Current: 65uA; Output Resistance: 15Ω; Energy Efficiency: 90%; PFM Mode: 不支持
U6 = S2B-PH-K-S(LF)(SN): 插针结构:1x2P;间距:2mm;安装方式:弯插;参考系列:PH;总PIN数:2P;排数:1;每排PIN数:2;行距:-;额定电流:2A;触头材质:黄铜;触头镀层:锡;工作温度:-25℃~+85℃;; Manufacturer: JST; AddInBom: yes; ModelId: 2eb659becec04affa6f990b56fa83cd20819f05c4eef4c71ace90d822a990e87; ModelName: CONN-TH_HR-PH2.0-WI-2P; ModelTransform: 236.22,303.149,0,180,0,0,0,95.472,-137.795; Pins Structure: 1x2P; Pitch: 2mm; Reference Series: PH; Number of PINs Per Row: 2; Current Rating: 2A; Voltage Rating: 100V; Plastic Material: PA66; Flame Retardant Rating: UL94V-0; Supplementary Features: 打K脚; Z-Height of the Board: 4.8mm; X-Length of Bottom Edge on Board (Spacing Line): 5.9mm; Y-Width of Bottom Edge on Board: 7.6mm
U7 = STM32F405RGT6: CPU内核:ARM Cortex-M4;CPU最大主频:168MHz;CPU位数:32 Bit;; Manufacturer: ST(意法半导体); Relevance: []; AddInBom: yes; ModelId: cd9de06618c44fcf82654c43a457f83c0819f05c4eef4c71ace90d822a990e87; ModelName: LQFP-64_L10.0-W10.0-H1.4-LS12.0-P0.50; ModelTransform: 472.441,472.441,0,0,0,0,0,0.465,0; CPU Maximum Speed: 168MHz; Core Size: 32 Bit; Program Storage Size: 1MB; Program Memory Type: FLASH; RAM Size: 192KB; Number of I/O: 51; ADC (Bit): 12bit; Oscillator Type: 内置; Voltage - Supply: 1.8V~3.6V
U8 = E73-2G4M08S1C: 核心芯片:nRF52840芯片;接口类型:I2C；USB；ISP；PWM；DMA；ADC；JTAG；SPI;发射功率:8dBm;通讯距离:120m;接收灵敏度:-95dBm；-103dBm;; Manufacturer: EBYTE(亿佰特); AddInBom: yes; ModelId: feb1956bb59f4276bdd6023c0ad9dfaf0819f05c4eef4c71ace90d822a990e87; ModelName: WIRELM-SMD_L18.0-W13.0-H3.0-E73-2G4M08S1C; ModelTransform: 511.81,708.66,0,0,0,0,0,-78.307,0; Wireless Standard: 蓝牙5.0；蓝牙4.2; Output Power(Max): 8dBm; Voltage - Supply: 3.3V; Receive  Current: 8.27mA; Send  Current: 17.05mA; Communication Distance: 120m
U9 = BMI270: 传感器类型:IMU(加速度计+陀螺仪);接口类型:I2C；SPI;; Manufacturer: Bosch(博世); AddInBom: yes; ModelId: 64f32784a16f466f897e9e56b6bbdf450819f05c4eef4c71ace90d822a990e87; ModelTransform: 118.11,98.425,0,180,0,0,-0.001,0.004,0; Accelerometer Sensing Axis: X,Y,Z; Acceleration Measurement Range (MAX): ±16g; Gyroscope Measurement Range (MAX): ±2000dps; Output Bits: 16bit; Voltage - Supply: 1.71V~3.6V; Cache Size: 2KB; Standby Current: 3.5uA
U10 = DS1021-2x13SF11-B: 插针结构:2x13P;间距:2.54mm;行距:2.54mm;圆针/方针:方针;安装方式:直插;排数:双排;总PIN位数:26P;额定电流:3A;额定电压:250V;触头材质:铜合金;触头镀层:金;工作温度:-40℃~+105℃;颜色:黑色;; Manufacturer: CONNFLY; AddInBom: yes; ModelId: 5550078eeab944d391459ddd01fa55c00819f05c4eef4c71ace90d822a990e87; ModelName: HDR-TH_26P-P2.54-M-LI-2X13P; ModelTransform: 1299.9974,196.85,0,0,0,0,0,0,-118.11; Pin Structure: 2x13P; Pitch: 2.54mm; Circluar Pins/Square Pins: 方针; Current Rating: 3A; Voltage Rating (Max): 250V
U19 = TPS63070模块: AddInBom: yes
USB1 = TYPE-C 16PIN 2MD(073): 连接器类型:Type-C;协议标准:-;公母:母;安装方式:卧贴;触点数量:16P;端口数量:1;额定电流 - 电源:3A;工作温度:-25℃~+85℃;; Manufacturer: SHOU HAN(首韩); AddInBom: yes; ModelId: 3a41b9ec9b654a0fad4d118405ec62900819f05c4eef4c71ace90d822a990e87; ModelName: USB-C-SMD_TYPE-C-6PIN-2MD-073; ModelTransform: 351.9678,298.4246,0,0,0,0,0,-47.244,-35.433; Gender: 母; Number of Contacts: 16P; Number of Ports: 1; Current Rating-Power: 3A; Voltage Rating: 5V; Connect-Disconnect Life: 1万次; Detection color: 黑色
X4 = X50328MSB2GI: 晶振类型:贴片晶振;频率:8MHz;常温频差:±10ppm;负载电容:20pF;频率稳定度:±20ppm;; Manufacturer: YXC(扬兴晶振); AddInBom: yes; ModelId: d7c39c66443246ff83c2003c1e1eb6f10819f05c4eef4c71ace90d822a990e87; ModelTransform: 196.85,125.984,0,0,0,0,0,0,0; Normal temperature Frequency Tolerance: ±10ppm; Load Capacitance: 20pF; Frequency Stability: ±20ppm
